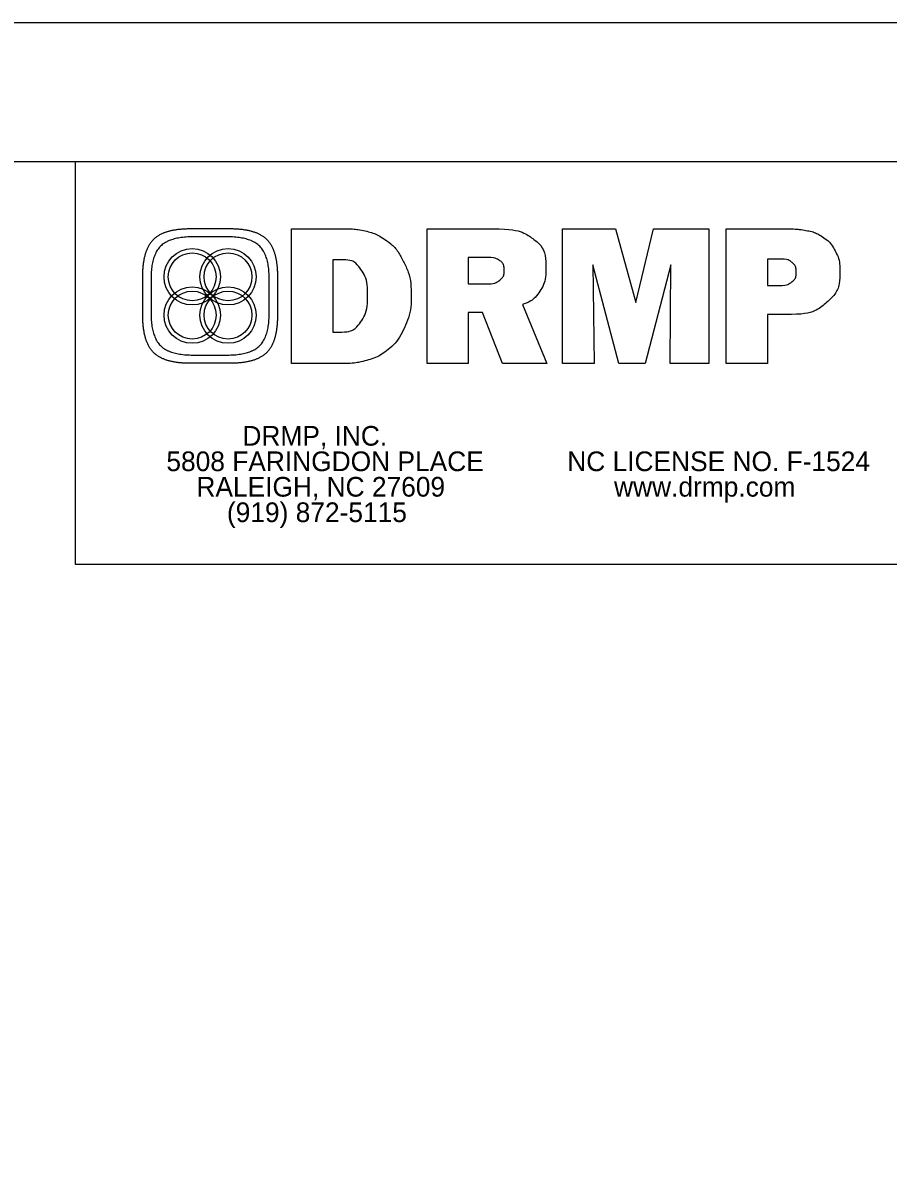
# Model space of a CAD drawing. Extents: x 573078 to 573156.2, y -55225.7 to -55195.8.
# Drawn here: x 573104.322 to 573107.444, y -55203.398 to -55199.298 of the extents above; entities that cross this region are included whole.
import ezdxf

# ---------------------------------------------------------------- set-up
doc = ezdxf.new("R2010")
doc.units = 0
for name, color, linetype in [('Pattern 1', 7, 'Continuous'), ('Pattern 2', 7, 'Continuous'), ('Sheet Plan CELL', 7, 'Continuous'), ('Sheet Plot Border Inside CELL', 7, 'Continuous')]:
    doc.layers.add(name, color=color, linetype=linetype)

msp = doc.modelspace()

# ---------------------------------------------------------------- linework, layer by layer
at = {"layer": 'Pattern 1'}
for p, q in [((573104.9279, -55200.041), (573105.0688, -55200.041)), ((573106.2698, -55200.5276), (573106.2698, -55200.0415)), ((573106.2698, -55200.0415), (573106.461, -55200.0415)), ((573106.461, -55200.0415), (573106.5338, -55200.3069)), ((573106.5338, -55200.3069), (573106.598, -55200.0415)), ((573106.598, -55200.0415), (573106.7977, -55200.0415)), ((573106.7977, -55200.0415), (573106.7977, -55200.5276)), ((573105.0602, -55200.0707), (573104.9365, -55200.0707)), ((573106.473, -55200.5276), (573106.3783, -55200.1711)), ((573106.3783, -55200.1711), (573106.3835, -55200.5276)), ((573106.6599, -55200.1711), (573106.5673, -55200.5276)), ((573106.6575, -55200.5276), (573106.6599, -55200.1711)), ((573104.7555, -55200.3543), (573104.7555, -55200.2134)), ((573105.2413, -55200.2134), (573105.2413, -55200.3543)), ((573104.7852, -55200.222), (573104.7852, -55200.3457)), ((573105.2115, -55200.3457), (573105.2115, -55200.222)), ((573104.9365, -55200.497), (573105.0602, -55200.497)), ((573105.0688, -55200.5268), (573104.9279, -55200.5268)), ((573106.3835, -55200.5276), (573106.2698, -55200.5276)), ((573106.5673, -55200.5276), (573106.473, -55200.5276)), ((573106.7977, -55200.5276), (573106.6575, -55200.5276))]:
    msp.add_line(p, q, dxfattribs=at)
for points in [[(573105.4719, -55200.5276), (573105.2914, -55200.5276), (573105.2914, -55200.0415), (573105.4784, -55200.0415)], [(573106.1248, -55200.3152), (573106.2124, -55200.5276), (573106.0527, -55200.5276), (573105.9805, -55200.3432), (573105.9296, -55200.3432), (573105.9296, -55200.5276), (573105.7817, -55200.5276), (573105.7817, -55200.0415), (573106.0192, -55200.0415)], [(573107.0949, -55200.3504), (573107.0086, -55200.3504), (573107.0086, -55200.5276), (573106.8596, -55200.5276), (573106.8596, -55200.0415), (573107.0668, -55200.0415)], [(573105.4784, -55200.1532), (573105.4404, -55200.1532), (573105.4404, -55200.4139), (573105.4739, -55200.4139)], [(573105.9983, -55200.1452), (573105.9296, -55200.1452), (573105.9296, -55200.2402), (573106.0004, -55200.2402)], [(573107.0576, -55200.1513), (573107.0086, -55200.1513), (573107.0086, -55200.2467), (573107.0487, -55200.2467)]]:
    msp.add_lwpolyline(points, dxfattribs=at)
for points, degree in [([(573104.7555, -55200.2134), (573104.7555, -55200.1186), (573104.8331, -55200.041), (573104.9279, -55200.041)], 2), ([(573105.0688, -55200.041), (573105.1636, -55200.041), (573105.2413, -55200.1186), (573105.2413, -55200.2134)], 2), ([(573105.4784, -55200.0415), (573105.5078, -55200.0415), (573105.5342, -55200.0441), (573105.5575, -55200.0493), (573105.5808, -55200.0546), (573105.6011, -55200.0627), (573105.6184, -55200.0736), (573105.6517, -55200.0946), (573105.6776, -55200.1235), (573105.6959, -55200.1603), (573105.7143, -55200.1972), (573105.7235, -55200.2385), (573105.7235, -55200.2843), (573105.7235, -55200.3249), (573105.7154, -55200.3629), (573105.6992, -55200.3983), (573105.683, -55200.4336), (573105.661, -55200.4618), (573105.6331, -55200.4827), (573105.6124, -55200.498), (573105.5889, -55200.5093), (573105.5628, -55200.5166), (573105.5366, -55200.5239), (573105.5064, -55200.5276), (573105.4719, -55200.5276)], 3), ([(573106.0192, -55200.0415), (573106.0828, -55200.0415), (573106.1304, -55200.0533), (573106.1621, -55200.0769), (573106.1938, -55200.1005), (573106.2097, -55200.136), (573106.2097, -55200.1834), (573106.2097, -55200.2163), (573106.2024, -55200.244), (573106.1879, -55200.2666), (573106.1735, -55200.2892), (573106.1524, -55200.3054), (573106.1248, -55200.3152)], 3), ([(573107.0668, -55200.0415), (573107.0992, -55200.0415), (573107.1261, -55200.0435), (573107.1474, -55200.0474), (573107.1688, -55200.0514), (573107.1865, -55200.0578), (573107.2006, -55200.0664), (573107.2235, -55200.0808), (573107.2407, -55200.0989), (573107.2525, -55200.1208), (573107.2642, -55200.1427), (573107.2701, -55200.1676), (573107.2701, -55200.1954), (573107.2701, -55200.2417), (573107.254, -55200.2792), (573107.2219, -55200.3077), (573107.1897, -55200.3362), (573107.1474, -55200.3504), (573107.0949, -55200.3504)], 3), ([(573104.9365, -55200.0707), (573104.8533, -55200.0707), (573104.7852, -55200.1388), (573104.7852, -55200.222)], 2), ([(573105.2115, -55200.222), (573105.2115, -55200.1388), (573105.1434, -55200.0707), (573105.0602, -55200.0707)], 2), ([(573105.4739, -55200.4139), (573105.5018, -55200.4139), (573105.5242, -55200.4019), (573105.541, -55200.378), (573105.5578, -55200.354), (573105.5662, -55200.3221), (573105.5662, -55200.2822), (573105.5662, -55200.2427), (573105.5582, -55200.2114), (573105.5423, -55200.1881), (573105.5265, -55200.1648), (573105.5051, -55200.1532), (573105.4784, -55200.1532)], 3), ([(573106.0004, -55200.2402), (573106.0177, -55200.2402), (573106.0318, -55200.2358), (573106.0428, -55200.2269), (573106.0537, -55200.218), (573106.0592, -55200.2066), (573106.0592, -55200.1927), (573106.0592, -55200.1768), (573106.0541, -55200.1649), (573106.0439, -55200.157), (573106.0338, -55200.1491), (573106.0186, -55200.1452), (573105.9983, -55200.1452)], 3), ([(573107.0487, -55200.2467), (573107.0688, -55200.2467), (573107.0844, -55200.2425), (573107.0956, -55200.234), (573107.1068, -55200.2256), (573107.1124, -55200.2139), (573107.1124, -55200.1988), (573107.1124, -55200.1836), (573107.1077, -55200.1718), (573107.0983, -55200.1636), (573107.089, -55200.1554), (573107.0754, -55200.1513), (573107.0576, -55200.1513)], 3), ([(573104.9279, -55200.5268), (573104.8331, -55200.5268), (573104.7555, -55200.4491), (573104.7555, -55200.3543)], 2), ([(573104.7852, -55200.3457), (573104.7852, -55200.4289), (573104.8533, -55200.497), (573104.9365, -55200.497)], 2), ([(573105.0602, -55200.497), (573105.1434, -55200.497), (573105.2115, -55200.4289), (573105.2115, -55200.3457)], 2), ([(573105.2413, -55200.3543), (573105.2413, -55200.4491), (573105.1636, -55200.5268), (573105.0688, -55200.5268)], 2)]:
    msp.add_open_spline(points, degree=degree, dxfattribs=at)
at = {"layer": 'Pattern 2'}
for centre, radius in [((573104.9337, -55200.2148), 0.1016), ((573104.9337, -55200.2148), 0.0864), ((573105.063, -55200.2148), 0.1016), ((573105.063, -55200.2148), 0.0864), ((573104.9337, -55200.3529), 0.1016), ((573105.063, -55200.3529), 0.1016), ((573104.9337, -55200.3529), 0.0864), ((573105.063, -55200.3529), 0.0864)]:
    msp.add_circle(centre, radius, dxfattribs=at)
at = {"layer": 'Sheet Plan CELL'}
for points in [[(573081.5142, -55199.7984), (573111.5142, -55199.7984), (573111.5142, -55220.7984), (573081.5142, -55220.7984)], [(573107.5132, -55201.252), (573104.5124, -55201.252), (573104.5124, -55199.7984), (573107.5132, -55199.7984)]]:
    msp.add_lwpolyline(points, close=True, dxfattribs=at)
at = {"layer": 'Sheet Plot Border Inside CELL'}
msp.add_lwpolyline([(573112.0142, -55199.2984), (573078.0142, -55199.2984), (573078.0142, -55221.2984), (573112.0142, -55221.2984)], close=True, dxfattribs=at)

# ---------------------------------------------------------------- texts
at = {"layer": 'Pattern 2'}
for s, height, p in [('DRMP, INC.', 0.07099, (573105.1149, -55200.8238)), ('5808 FARINGDON PLACE', 0.070991, (573104.8406, -55200.9157)), ('NC LICENSE NO. F-1524', 0.070991, (573106.2865, -55200.9157)), ('RALEIGH, NC 27609', 0.070991, (573104.9489, -55201.0076)), ('www.drmp.com', 0.070991, (573106.4554, -55201.0076)), ('(919) 872-5115', 0.070991, (573105.059, -55201.0995))]:
    msp.add_text(s, height=height, rotation=360, dxfattribs=at).set_placement(p)

doc.saveas('drawing.dxf')
